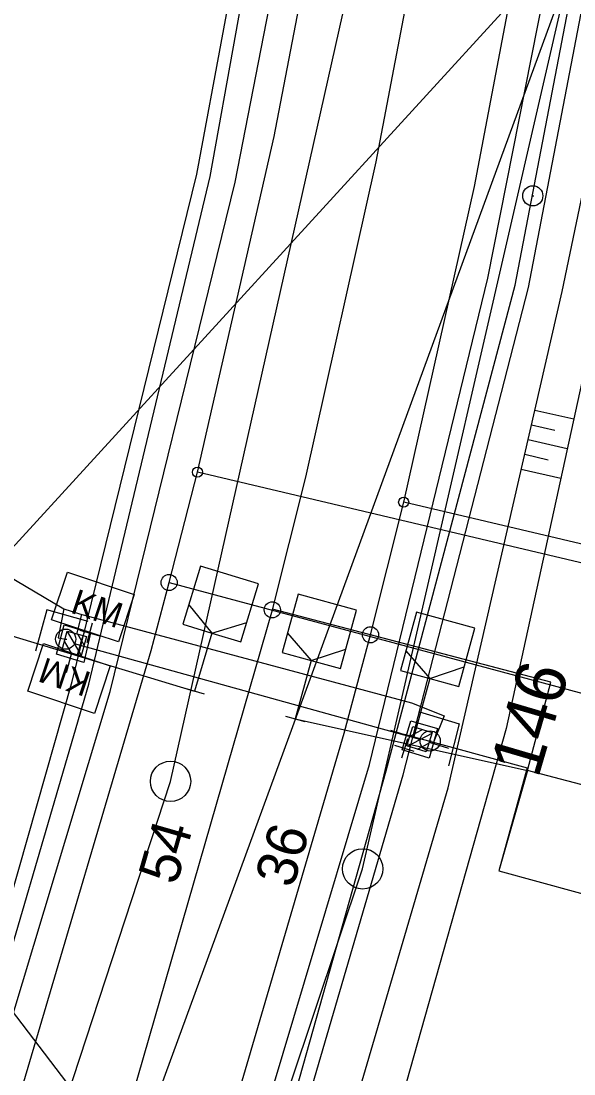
# Model space of a CAD drawing. Extents: x -598638 to -597933, y -1164002 to -1161904.
# Drawn here: x -598271.6 to -598244.2, y -1163425.1 to -1163372.9 of the extents above; entities that cross this region are included whole.
import ezdxf

# ---------------------------------------------------------------- set-up
doc = ezdxf.new("R2010")
doc.units = 0
for name, color, linetype in [('Vrstva 1', 7, 'Continuous'), ('Vrstva 11', 7, 'Continuous'), ('Vrstva 12', 7, 'Continuous'), ('Vrstva 17', 7, 'Continuous'), ('Vrstva 25', 7, 'Continuous'), ('Vrstva 26', 7, 'Continuous'), ('Vrstva 4', 7, 'Continuous'), ('Vrstva 43', 7, 'Continuous'), ('Vrstva 44', 7, 'Continuous'), ('Vrstva 48', 7, 'Continuous'), ('Vrstva 49', 7, 'Continuous'), ('Vrstva 51', 7, 'Continuous'), ('Vrstva 63', 7, 'Continuous'), ('Vrstva 7', 7, 'Continuous')]:
    doc.layers.add(name, color=color, linetype=linetype)

msp = doc.modelspace()

# ---------------------------------------------------------------- linework, layer by layer
at = {"layer": 'Vrstva 1'}
for p, q in [((-598174.849, -1163416.038), (-598262.877, -1163395.251)), ((-598264.28, -1163400.716), (-598191.237, -1163420.309))]:
    msp.add_line(p, q, dxfattribs=at)
for points in [[(-598259.161, -1163402.069), (-598257.506, -1163395.492), (-598254.014, -1163379.874), (-598251.435, -1163366.348), (-598248.154, -1163344.226), (-598246.19, -1163325.096), (-598245.046, -1163305.011), (-598244.933, -1163298.014), (-598244.77, -1163287.888)], [(-598254.294, -1163403.303), (-598252.648, -1163396.738), (-598249.139, -1163381.102), (-598246.501, -1163367.254), (-598243.179, -1163344.93), (-598241.198, -1163325.59), (-598240.025, -1163305.166), (-598239.731, -1163287.87)], [(-598264.28, -1163400.716), (-598262.877, -1163395.251), (-598259.069, -1163378.617), (-598256.287, -1163364.167), (-598253.132, -1163343.401), (-598250.9, -1163321.936)], [(-598129.944, -1163393.23), (-598184.352, -1163380.422), (-598191.576, -1163411.115), (-598252.648, -1163396.738)], [(-598301.845, -1163499.63), (-598294.731, -1163484.985), (-598286.716, -1163466.876), (-598278.237, -1163445.237), (-598271.696, -1163426.176), (-598265.175, -1163404.08), (-598264.28, -1163400.716)], [(-598295.824, -1163499.94), (-598294.221, -1163496.623), (-598290.233, -1163488.369), (-598281.741, -1163469.161), (-598273.542, -1163448.198), (-598266.682, -1163428.135), (-598259.161, -1163402.069)], [(-598192.218, -1163424.255), (-598246.5, -1163410.019), (-598245.354, -1163405.648), (-598259.151, -1163402.029)], [(-598291.348, -1163502.182), (-598289.74, -1163498.855), (-598285.789, -1163490.683), (-598277.189, -1163471.281), (-598268.83, -1163449.929), (-598261.944, -1163429.787), (-598255.593, -1163408.171), (-598254.294, -1163403.303)], [(-598192.218, -1163424.255), (-598246.5, -1163410.019), (-598245.354, -1163405.648), (-598254.294, -1163403.303)]]:
    msp.add_lwpolyline(points, dxfattribs=at)
for centre, radius in [((-598262.877, -1163395.251), 0.25), ((-598252.648, -1163396.738), 0.25), ((-598264.28, -1163400.716), 0.4), ((-598259.161, -1163402.069), 0.4), ((-598254.294, -1163403.303), 0.4)]:
    msp.add_circle(centre, radius, dxfattribs=at)
at = {"layer": 'Vrstva 11'}
for p, q in [((-598268.862, -1163403.267), (-598268.6, -1163402.291)), ((-598268.631, -1163404.33), (-598269.32, -1163403.134)), ((-598268.493, -1163403.818), (-598268.808, -1163403.271)), ((-598269.126, -1163404.221), (-598269.474, -1163403.616)), ((-598269.118, -1163404.219), (-598269.38, -1163405.189)), ((-598252.334, -1163408.335), (-598253.293, -1163408.038)), ((-598252.462, -1163408.818), (-598251.242, -1163408.172)), ((-598252.336, -1163408.327), (-598251.718, -1163408)), ((-598251.956, -1163408.974), (-598251.398, -1163408.679)), ((-598251.392, -1163408.625), (-598250.427, -1163408.922))]:
    msp.add_line(p, q, dxfattribs=at)
for points in [[(-598269.603, -1163404.093), (-598269.343, -1163403.127), (-598268.377, -1163403.387), (-598268.637, -1163404.353)], [(-598252.191, -1163407.855), (-598251.235, -1163408.149), (-598251.529, -1163409.105), (-598252.485, -1163408.811)]]:
    msp.add_lwpolyline(points, close=True, dxfattribs=at)
for points in [[(-598269.603, -1163404.093), (-598269.343, -1163403.127), (-598268.377, -1163403.387), (-598268.637, -1163404.353), (-598269.603, -1163404.093)], [(-598268.99, -1163403.74), (-598251.86, -1163408.48)], [(-598252.191, -1163407.855), (-598251.235, -1163408.149), (-598251.529, -1163409.105), (-598252.485, -1163408.811), (-598252.191, -1163407.855)]]:
    msp.add_lwpolyline(points, dxfattribs=at)
at = {"layer": 'Vrstva 12'}
for points in [[(-598268.17, -1163403.2), (-598268.51, -1163404.68), (-598269.87, -1163404.26), (-598269.48, -1163402.81), (-598268.17, -1163403.2)], [(-598252.72, -1163409.01), (-598252.3, -1163407.56), (-598250.97, -1163407.95), (-598251.39, -1163409.42), (-598252.72, -1163409.01)]]:
    msp.add_lwpolyline(points, dxfattribs=at)
at = {"layer": 'Vrstva 17'}
for points in [[(-598268.3, -1163402.64), (-598270.34, -1163402.07), (-598270.91, -1163404.12)], [(-598251.92, -1163407.1), (-598249.9, -1163407.72), (-598250.42, -1163409.79)]]:
    msp.add_lwpolyline(points, dxfattribs=at)
at = {"layer": 'Vrstva 25'}
for p, q in [((-598269.46, -1163403.522), (-598269.36, -1163403.522)), ((-598251.383, -1163408.563), (-598251.283, -1163408.563))]:
    msp.add_line(p, q, dxfattribs=at)
for centre in [(-598269.41, -1163403.522), (-598251.333, -1163408.563)]:
    msp.add_circle(centre, 0.5, dxfattribs=at)
at = {"layer": 'Vrstva 26'}
for points in [[(-598285.855, -1163392.347), (-598269.505, -1163402.021), (-598268.731, -1163402.266), (-598252.259, -1163406.667), (-598250.635, -1163407.319), (-598251.158, -1163408.595)], [(-598269.505, -1163402.021), (-598269.782, -1163403.458), (-598269.41, -1163403.522)]]:
    msp.add_lwpolyline(points, dxfattribs=at)
at = {"layer": 'Vrstva 4'}
for points in [[(-598321.684, -1163563.952), (-598314.649, -1163552.341), (-598302.065, -1163529.781), (-598292.77, -1163512.02), (-598281.731, -1163489.572), (-598274.163, -1163472.668), (-598266.066, -1163452.17), (-598258.953, -1163431.709), (-598252.674, -1163410.241), (-598246.46, -1163386.104), (-598243.144, -1163368.884), (-598239.955, -1163345.756), (-598237.56, -1163323.253), (-598236.679, -1163305.47), (-598236.283, -1163282.744), (-598236.431, -1163244.569), (-598236.596, -1163214.625), (-598236.873, -1163174.881), (-598236.229, -1163131.239), (-598234.781, -1163108.249), (-598234.285, -1163099.455), (-598231.787, -1163078.342)], [(-598283.36, -1163489.15), (-598275.736, -1163471.917), (-598267.551, -1163451.028), (-598260.793, -1163431.262), (-598254.345, -1163409.722), (-598248.47, -1163385.636), (-598245.045, -1163368.352), (-598241.712, -1163345.6), (-598239.462, -1163322.753), (-598238.478, -1163305.467), (-598238.203, -1163283.28), (-598238.406, -1163245.16), (-598238.376, -1163215.168), (-598238.53, -1163175.26), (-598238.394, -1163131.328), (-598237.202, -1163108.683), (-598236.122, -1163097.625), (-598233.737, -1163078.205)], [(-598307.376, -1163503.64), (-598306.256, -1163500.72), (-598304.527, -1163496.743), (-598299.478, -1163486.144), (-598290.117, -1163465.204), (-598280.795, -1163442.724), (-598274.814, -1163425.66), (-598269.09, -1163405.616), (-598262.907, -1163380.487), (-598260.225, -1163366.071), (-598256.638, -1163342.661), (-598254.612, -1163322.432), (-598252.977, -1163304.928), (-598251.437, -1163287.268), (-598250.068, -1163266.224), (-598248.818, -1163245.446), (-598248.467, -1163214.545), (-598248.623, -1163173.63), (-598248.072, -1163131.254), (-598247.596, -1163128.349)]]:
    msp.add_lwpolyline(points, dxfattribs=at)
at = {"layer": 'Vrstva 43'}
for centre in [(-598264.209, -1163410.565), (-598254.684, -1163414.899)]:
    msp.add_circle(centre, 1, dxfattribs=at)
at = {"layer": 'Vrstva 44'}
for points in [[(-598295.758, -1163493.483), (-598278.118, -1163452.874), (-598264.209, -1163410.565), (-598254.468, -1163367.19), (-598248.62, -1163321.577), (-598253.497, -1163320.887), (-598249.615, -1163272.581), (-598247.635, -1163222.481), (-598247.486, -1163176.779), (-598247.442, -1163130.148), (-598244.014, -1163084.171), (-598235.33, -1163037.762), (-598224.817, -1163002.559), (-598219.379, -1163002.169), (-598206.652, -1162968.487), (-598191.401, -1162936.053), (-598173.754, -1162904.506), (-598155.689, -1162873.083), (-598136.14, -1162838.446), (-598116.776, -1162804.197)], [(-598286.823, -1163498.793), (-598268.977, -1163457.491), (-598254.684, -1163414.899), (-598244.494, -1163370.7), (-598238.629, -1163323.594), (-598237.183, -1163277.386), (-598237.387, -1163227.403), (-598237.546, -1163176.839), (-598237.218, -1163130.355), (-598233.358, -1163084.011), (-598224.142, -1163038.365), (-598215.269, -1163005.578), (-598224.817, -1163002.559)], [(-598403.637, -1163432.342), (-598346.555, -1163418.577), (-598345.216, -1163418.65), (-598343.663, -1163418.367), (-598342.098, -1163418.162), (-598292.973, -1163414.355), (-598291.233, -1163414.37), (-598274.654, -1163418.559), (-598263.203, -1163433.575), (-598253.773, -1163465.608), (-598253.123, -1163466.538), (-598245.997, -1163476.61), (-598234.314, -1163480.567), (-598232.066, -1163480.596), (-598231.165, -1163480.525)]]:
    msp.add_lwpolyline(points, dxfattribs=at)
at = {"layer": 'Vrstva 48'}
for p, q in [((-598244.216, -1163392.631), (-598246.143, -1163392.187)), ((-598245.15, -1163393.185), (-598246.311, -1163392.918)), ((-598244.536, -1163394.096), (-598246.479, -1163393.649)), ((-598245.477, -1163394.649), (-598246.647, -1163394.38)), ((-598244.857, -1163395.562), (-598246.816, -1163395.111))]:
    msp.add_line(p, q, dxfattribs=at)
at = {"layer": 'Vrstva 49'}
for points in [[(-598312.315, -1163561.929), (-598312.053, -1163560.13), (-598297.72, -1163533.783), (-598287.557, -1163512.375), (-598279.159, -1163492.971), (-598271.476, -1163473.929), (-598263.327, -1163452.767), (-598256.849, -1163432.711), (-598250.447, -1163410.888), (-598244.786, -1163386.292), (-598240.759, -1163366.985), (-598236.936, -1163346.431), (-598233.733, -1163325.755), (-598232.232, -1163311.779)], [(-598232.232, -1163311.779), (-598233.089, -1163326.313), (-598236.119, -1163345.209), (-598237.446, -1163358.355), (-598243.268, -1163388.291), (-598247.561, -1163407.939), (-598253.242, -1163428.023), (-598260.918, -1163451.594), (-598268.495, -1163470.375), (-598277.5, -1163493.166), (-598288.559, -1163518.332), (-598296.048, -1163535.039), (-598302.041, -1163547.928), (-598308.079, -1163558.087)]]:
    msp.add_lwpolyline(points, dxfattribs=at)
at = {"layer": 'Vrstva 51'}
for points in [[(-598298.888, -1163486.593), (-598289.113, -1163465.583), (-598279.905, -1163442.964), (-598274.107, -1163425.699), (-598268.268, -1163405.757), (-598262.238, -1163380.596), (-598259.701, -1163366.461), (-598255.999, -1163342.847), (-598253.859, -1163322.319), (-598252.407, -1163304.609), (-598250.982, -1163286.31), (-598249.458, -1163266.6), (-598248.128, -1163245.447), (-598247.963, -1163214.31), (-598248.01, -1163173.778), (-598247.475, -1163130.652), (-598247.596, -1163128.349), (-598246.685, -1163112.866), (-598245.177, -1163096.514), (-598242.921, -1163076.624)], [(-598305.922, -1163504.285), (-598297.335, -1163487.137), (-598287.92, -1163465.981), (-598279.035, -1163443.103), (-598273.208, -1163425.978), (-598267.2, -1163406.108), (-598261.011, -1163380.887), (-598258.166, -1163366.304), (-598254.569, -1163343.143), (-598252.435, -1163322.084), (-598250.965, -1163305.051), (-598249.488, -1163286.133), (-598247.962, -1163266.793), (-598246.718, -1163245.404), (-598246.637, -1163214.417), (-598246.633, -1163173.748), (-598246.347, -1163129.422), (-598245.484, -1163112.939), (-598244.076, -1163096.672), (-598241.475, -1163076.865)], [(-598282.309, -1163489.477), (-598274.667, -1163472.413), (-598266.77, -1163451.853), (-598259.621, -1163431.675), (-598253.513, -1163410.04), (-598247.112, -1163385.98), (-598243.846, -1163368.944), (-598240.561, -1163345.639), (-598238.081, -1163322.667), (-598237.343, -1163305.453), (-598236.795, -1163282.909), (-598237.051, -1163244.829), (-598237.298, -1163214.833), (-598237.439, -1163175.203), (-598237.167, -1163131.222), (-598235.767, -1163108.629), (-598234.985, -1163097.818), (-598232.528, -1163078.41)]]:
    msp.add_lwpolyline(points, dxfattribs=at)
at = {"layer": 'Vrstva 63'}
for p in [(-598304.703, -1163434.652), (-598303.776, -1163532.286)]:
    msp.add_line(p, (-598243.435, -1163367.735), dxfattribs=at)
at = {"layer": 'Vrstva 7'}
for p, q in [((-598246.297, -1163381.563), (-598246.197, -1163381.563)), ((-598291.713, -1163397.458), (-598263.021, -1163406.09)), ((-598268.088, -1163402.735), (-598268.356, -1163403.699)), ((-598268.704, -1163403.083), (-598267.74, -1163403.351)), ((-598268.65, -1163403.698), (-598268.453, -1163403.107)), ((-598262.157, -1163403.217), (-598263.021, -1163406.09)), ((-598268.65, -1163403.698), (-598268.847, -1163404.289)), ((-598257.229, -1163404.582), (-598258.029, -1163407.473)), ((-598251.357, -1163405.468), (-598252.148, -1163408.362)), ((-598263.5, -1163405.946), (-598262.542, -1163406.234)), ((-598258.511, -1163407.34), (-598257.547, -1163407.606)), ((-598252.459, -1163408.459), (-598252.761, -1163409.413)), ((-598252.63, -1163408.23), (-598251.666, -1163408.494)), ((-598252.133, -1163409.087), (-598253.087, -1163408.785))]:
    msp.add_line(p, q, dxfattribs=at)
for points in [[(-598262.157, -1163403.217), (-598260.72, -1163403.649), (-598259.855, -1163400.776), (-598262.729, -1163399.912), (-598263.593, -1163402.785), (-598262.157, -1163403.217)], [(-598257.229, -1163404.582), (-598255.783, -1163404.982), (-598254.983, -1163402.09), (-598257.874, -1163401.29), (-598258.675, -1163404.182), (-598257.229, -1163404.582)], [(-598263.305, -1163401.825), (-598262.157, -1163403.217), (-598260.431, -1163402.69)], [(-598251.357, -1163405.468), (-598249.91, -1163405.864), (-598249.119, -1163402.97), (-598252.013, -1163402.179), (-598252.804, -1163405.073), (-598251.357, -1163405.468)], [(-598258.407, -1163403.216), (-598257.229, -1163404.582), (-598255.516, -1163404.016)], [(-598252.54, -1163404.106), (-598251.357, -1163405.468), (-598249.646, -1163404.897)], [(-598258.029, -1163407.473), (-598246.5, -1163410.019), (-598247.923, -1163414.996), (-598215.049, -1163423.983)], [(-598252.148, -1163408.362), (-598246.529, -1163409.898), (-598247.923, -1163414.996), (-598215.049, -1163423.983)]]:
    msp.add_lwpolyline(points, dxfattribs=at)
for points in [[(-598270.105, -1163402.556), (-598269.32, -1163400.2), (-598266.011, -1163401.304), (-598266.797, -1163403.66)], [(-598267.195, -1163404.84), (-598267.98, -1163407.196), (-598271.289, -1163406.092), (-598270.503, -1163403.736)]]:
    msp.add_lwpolyline(points, close=True, dxfattribs=at)
msp.add_circle((-598246.247, -1163381.563), 0.5, dxfattribs=at)

# ---------------------------------------------------------------- texts
at = {"layer": 'Vrstva 11'}
msp.add_text('146', height=2.5, rotation=73.628, dxfattribs=at).set_placement((-598245.991, -1163410.469))
at = {"layer": 'Vrstva 43'}
for s, rotation, p in [('54', 73.9052, (-598263.921, -1163415.754)), ('36', 73.6267, (-598258.142, -1163415.908))]:
    msp.add_text(s, height=2, rotation=rotation, dxfattribs=at).set_placement(p)
at = {"layer": 'Vrstva 7'}
for rotation, p in [(341.5527, (-598269.222, -1163402.198)), (161.5527, (-598268.078, -1163405.198))]:
    msp.add_text('KM', height=1.2469, rotation=rotation, dxfattribs=at).set_placement(p)

doc.saveas('drawing.dxf')
